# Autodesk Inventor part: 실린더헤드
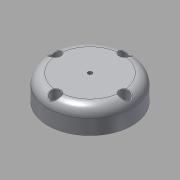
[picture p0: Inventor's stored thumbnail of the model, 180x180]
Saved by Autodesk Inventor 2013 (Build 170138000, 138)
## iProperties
Created: 2016-11
Part Number: 실린더헤드
Material: 알루미늄 6061
Document SubType Name: Modeling
Designer: mduedu
Density: 2.71 g/cm^3
Mass: 284.819 g
Surface Area: 227.25 cm^2
Volume: 105.099 cm^3
Author: mduedu
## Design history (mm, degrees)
sketch "스케치1"
  geometry: C1 r 42.5 at (0, 0); 1 further point
  constraints: 1 centre point, 1 coincident
  dimensions: "d0" = 85 diameter of C1
extrude "돌출1" new body sketch "스케치1" distance "d1" = 25; taper "d2" = 0 deg
fillet "모깎기1" dims "d3" = 10
sketch "스케치2"
  geometry: C1 r 30 at (0, 0); 1 further point
  constraints: 1 centre point, 1 coincident
  dimensions: "d4" = 60 diameter of C1
extrude "돌출2" join sketch "스케치2" distance "d5" = 5; taper "d6" = 0 deg
sketch "스케치3"
  geometry: C1 r 25 at (0, 0); 1 further point
  constraints: 1 centre point, 1 coincident
  dimensions: "d7" = 50 diameter of C1
extrude "돌출3" cut sketch "스케치3" distance "d8" = 20; taper "d9" = 0 deg
hole "구멍1" diameter "d12" = 4.134; stored, may be unused: countersink angle "d16" = 90 deg, drill point angle "d18" = 118 deg; dims "d10" = 10, "d11" = 10, "d13" = 6, "d14" = 4, "d15" = 2, "d17" = 8
chamfer "모따기1" distance "d19" = 1; stored, may be unused: second distance "d20" = 2, angle "d21" = 45 deg
fillet "모깎기2" dims "d22" = 3
sketch "스케치4"
  geometry: C1 r 17.5 at (0, 0); 1 further point
  constraints: 1 centre point, 1 coincident
  dimensions: "d23" = 35 diameter of C1
extrude "돌출4" cut sketch "스케치4" distance "d24" = 2; taper "d25" = 0 deg
fillet "모깎기3" dims "d26" = 0.5
sketch "스케치5" dims "d32" = 70
  geometry: C1 r 5 at (0, 35); 3 further points
  constraints: 2 coincident, 2 vertical alignment, 1 centre point, 2 other
  dimensions: "d33" = 10 diameter of C1
extrude "돌출5" cut sketch "스케치5" distance "d34" = 10; taper "d35" = 0 deg
sketch "스케치6" dims "d39" = 70
  geometry: 6 further points
  constraints: 2 vertical alignment, 1 coincident, 7 other
  dimensions: "d42" = 360 deg dimension on point (0, -35) point (0, 0) (derived)
sketch "스케치7"
  geometry: 4 further points
  constraints: 4 other
hole "구멍2" sketch "스케치7" at (0, 70), (-35, 35), (35, 35), (0, 0) diameter "d44" = 5.5; stored, may be unused: countersink angle "d48" = 90 deg, drill point angle "d50" = 0 deg; dims "d45" = 6, "d46" = 4, "d47" = 2, "d49" = 8
fillet "모깎기4" dims "d51" = 0.5
node "솔리드1"
pattern_circular "원형 패턴1" dims angle "d37" = 360 deg
